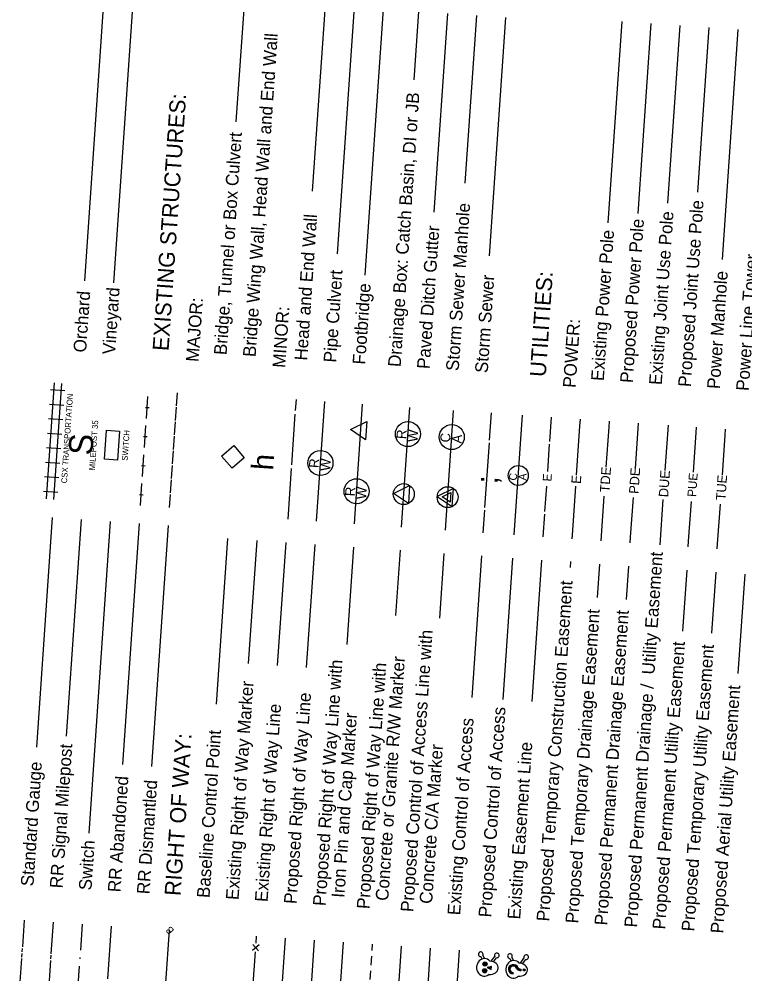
# Model space of a CAD drawing. Extents: x 2598107 to 2605763, y 726018 to 731166.
# Drawn here: x 2603520 to 2604643, y 728143 to 729620 of the extents above; entities that cross this region are included whole.
import ezdxf

# ---------------------------------------------------------------- set-up
doc = ezdxf.new("R2010")
doc.units = 0
for name, color, linetype in [('Prop Easement Permanent Drainage Utility', 7, 'Continuous'), ('Prop EOT', 7, 'Continuous'), ('Sheet Symbology CELL', 7, 'Continuous')]:
    doc.layers.add(name, color=color, linetype=linetype)

msp = doc.modelspace()

# ---------------------------------------------------------------- linework, layer by layer
at = {"layer": 'Prop Easement Permanent Drainage Utility'}
for p, q in [((2604519.7, 728921.8), (2604524.5, 728991.9)), ((2604511.7, 728806.7), (2604516.6, 728876.9))]:
    msp.add_line(p, q, dxfattribs=at)
at = {"layer": 'Prop EOT'}
msp.add_lwpolyline([(2603849.6, 728925.2), (2603833.3, 728943.9), (2603852, 728960.3), (2603868.4, 728941.5)], close=True, dxfattribs=at)
at = {"layer": 'Sheet Symbology CELL'}
for p, q in [((2603652.7, 729675.1), (2603621, 729215.1)), ((2603697.6, 729672), (2603665.9, 729212)), ((2603868.5, 729650.5), (2603855.5, 729461)), ((2603993.3, 729641.9), (2603973.4, 729353.9)), ((2604038.2, 729638.8), (2604011.9, 729256.8)), ((2604083.1, 729635.7), (2604054.7, 729223.9)), ((2604137.9, 729632), (2604130.6, 729526)), ((2604182.8, 729628.9), (2604161.6, 729321.5)), ((2604227.7, 729625.8), (2604209.8, 729366.1)), ((2604272.6, 729622.7), (2604247.2, 729254.1)), ((2604452.6, 729616.6), (2604431.1, 729305.2)), ((2604497.5, 729613.5), (2604477.2, 729319.6)), ((2604542.4, 729610.4), (2604523.4, 729335.4)), ((2604587.3, 729607.3), (2604569.7, 729352.5)), ((2604632.2, 729604.2), (2604607.7, 729248.4)), ((2603573.2, 729034.8), (2603574.7, 729057.3)), ((2603584.4, 729034), (2603585.9, 729056.5)), ((2603590.8, 729044.9), (2603568.3, 729046.4)), ((2603763.4, 729021.7), (2603764.8, 729041.9)), ((2603589.2, 729022.4), (2603566.8, 729024)), ((2603571.6, 729012.4), (2603573.2, 729034.8)), ((2603582.9, 729011.6), (2603584.4, 729034)), ((2603717, 729002.4), (2603719.3, 729036)), ((2603947.7, 729014.7), (2603948.9, 729031.5)), ((2603980, 728843.3), (2603992.8, 729028.5)), ((2604038.7, 728839.3), (2604051.4, 729024.4)), ((2603570.1, 728989.9), (2603571.6, 729012.4)), ((2603581.3, 728989.2), (2603582.9, 729011.6)), ((2603715.4, 729019.4), (2603721, 729019)), ((2603761.9, 728999.3), (2603763.3, 729019.5)), ((2603941.9, 728930.5), (2603947.3, 729009.1)), ((2604111.6, 728834.2), (2604124.4, 729019.4)), ((2604179.5, 728829.6), (2604192.3, 729014.7)), ((2604247.9, 728968.9), (2604250.8, 729010.7)), ((2604286, 728822.2), (2604298.7, 729007.4)), ((2603587.7, 729000), (2603565.2, 729001.5)), ((2603760.4, 728976.8), (2603761.7, 728997)), ((2604341, 728966.7), (2604343.6, 729004.3)), ((2604387.8, 728990.2), (2604388.5, 729001.2)), ((2604432.8, 728988.8), (2604433.4, 728998.1)), ((2604477.7, 728986.7), (2604478.3, 728995)), ((2603586.1, 728977.5), (2603563.7, 728979.1)), ((2603568.5, 728967.5), (2603570.1, 728989.9)), ((2603579.8, 728966.7), (2603581.3, 728989.2)), ((2603713.9, 728957.5), (2603716.2, 728991.1)), ((2604048.6, 728983.9), (2604048.6, 728983.9)), ((2604382.5, 728914.5), (2604387.8, 728990.2)), ((2604428.5, 728927.1), (2604432.8, 728988.8)), ((2604473.5, 728925), (2604477.7, 728986.7)), ((2604563.3, 728918.9), (2604567.5, 728980.6)), ((2604567.5, 728980.6), (2604568.1, 728988.9)), ((2604612.4, 728976.4), (2604613, 728985.8)), ((2603567, 728945), (2603568.5, 728967.5)), ((2603578.2, 728944.3), (2603579.8, 728966.7)), ((2603712.3, 728974.5), (2603717.9, 728974.1)), ((2603758.8, 728954.4), (2603760.2, 728974.6)), ((2604240.7, 728864.7), (2604247.6, 728964.4)), ((2604608.1, 728914.7), (2604612.4, 728976.4)), ((2603584.6, 728955.1), (2603562.2, 728956.6)), ((2603757.3, 728931.9), (2603758.7, 728952.1)), ((2604337.8, 728920.2), (2604340.7, 728962.3)), ((2603583.1, 728932.7), (2603560.6, 728934.2)), ((2603565.4, 728922.6), (2603567, 728945)), ((2603576.7, 728921.8), (2603578.2, 728944.3)), ((2603710.8, 728912.6), (2603713.1, 728946.2)), ((2603563.9, 728900.1), (2603565.4, 728922.6)), ((2603575.1, 728899.4), (2603576.7, 728921.8)), ((2603709.2, 728929.6), (2603714.8, 728929.2)), ((2603755.7, 728909.5), (2603757.1, 728929.7)), ((2603936.1, 728846.3), (2603941.5, 728924.9)), ((2603581.5, 728910.2), (2603559.1, 728911.8)), ((2603754.2, 728887), (2603755.6, 728907.2)), ((2603580, 728887.8), (2603557.5, 728889.3)), ((2603562.4, 728877.7), (2603563.9, 728900.1)), ((2603573.6, 728876.9), (2603575.1, 728899.4)), ((2603707.7, 728867.7), (2603710, 728901.4)), ((2604333.6, 728858.4), (2604336.3, 728897.7)), ((2604376.2, 728821.9), (2604381.4, 728897.7)), ((2603706.1, 728884.7), (2603711.7, 728884.3)), ((2603752.6, 728864.6), (2603754, 728884.8)), ((2604115.1, 728885.2), (2604115.1, 728885.2)), ((2604183, 728880.5), (2604183, 728880.5)), ((2604421.2, 728820.5), (2604425.4, 728882.2)), ((2604466.1, 728818.4), (2604470.4, 728880.1)), ((2604555.9, 728812.3), (2604560.2, 728874)), ((2604238, 728825.5), (2604240.4, 728860.2)), ((2604600.8, 728808.1), (2604605, 728869.8)), ((2603571.1, 728849.1), (2603546.6, 728493.6)), ((2603616, 728846), (2603592.9, 728510.4)), ((2604330.9, 728819.1), (2604333.3, 728853.9)), ((2603660.9, 728843), (2603627.7, 728360.5)), ((2603705.8, 728839.9), (2603680.1, 728466.9)), ((2603750.7, 728836.8), (2603725, 728463.8)), ((2603750.7, 728836.8), (2603725, 728463.8)), ((2603842.6, 728816.6), (2603824.9, 728560.2)), ((2604375.8, 728816), (2604376.2, 728821.9)), ((2604420.6, 728812.9), (2604421.2, 728820.5)), ((2604465.5, 728809.9), (2604466.1, 728818.4)), ((2603887.5, 728813.5), (2603874.3, 728622.9)), ((2603932.4, 728810.4), (2603919.2, 728619.8)), ((2603977.3, 728807.3), (2603964.1, 728616.7)), ((2604037.5, 728803.2), (2604027.1, 728652.5)), ((2604555.4, 728803.7), (2604555.9, 728812.3)), ((2604600.2, 728800.6), (2604600.8, 728808.1)), ((2604109.4, 728798.2), (2604102.5, 728697.2)), ((2604177.3, 728793.5), (2604170.4, 728693.4)), ((2604235.6, 728789.5), (2604220.5, 728570.6)), ((2604283.5, 728786.2), (2604268.4, 728567.3)), ((2604328.4, 728783.1), (2604313.3, 728564.2)), ((2604373.3, 728780.9), (2604372.7, 728771.5)), ((2604418.2, 728777), (2604414.6, 728725)), ((2604463.1, 728773.9), (2604459.5, 728721.9)), ((2604552.9, 728767.7), (2604546.4, 728673.1)), ((2604597.8, 728764.6), (2604591.3, 728670)), ((2604642.7, 728761.5), (2604632.1, 728607.8)), ((2603525.4, 728184.6), (2603528.2, 728226)), ((2603569.7, 728173.8), (2603573.1, 728222.9)), ((2603615.2, 728179.4), (2603618, 728219.8)), ((2603657.3, 728135.3), (2603662.9, 728216.7)), ((2603747.1, 728129.1), (2603752.7, 728210.5)), ((2603886.6, 728190.2), (2603887.4, 728201.2)), ((2603919.9, 728018.6), (2603932.3, 728198.1)), ((2603919.9, 728018.6), (2603932.3, 728198.1)), ((2603964.8, 728015.5), (2603977.1, 728195.1)), ((2603964.8, 728015.5), (2603977.1, 728195.1)), ((2603524.8, 728176.7), (2603525.2, 728182.3)), ((2603891.2, 728187.9), (2603881.1, 728179.1)), ((2603890.5, 728178.5), (2603881.8, 728188.5)), ((2604009.7, 728012.4), (2604022, 728192)), ((2604009.7, 728012.4), (2604022, 728192)), ((2604066.3, 728178.9), (2604066.9, 728188.9)), ((2604106.5, 728108.5), (2604111.8, 728185.8)), ((2604151.5, 728107.4), (2604156.7, 728182.7)), ((2604196.4, 728103.8), (2604201.6, 728179.6)), ((2603519.9, 728104.9), (2603524.1, 728166.6)), ((2603524.3, 728168.8), (2603524.7, 728174.5)), ((2603569.2, 728166), (2603569.6, 728171.6)), ((2603614.3, 728165.9), (2603614.4, 728168.2)), ((2603883.7, 728148.7), (2603885.7, 728176.8)), ((2604064.7, 728156.5), (2604065.6, 728170)), ((2604234.2, 728169.6), (2604236.3, 728165.8)), ((2604237.2, 728171.2), (2604239.8, 728166.5)), ((2604250.4, 728162.3), (2604255.9, 728169.9)), ((2604253.9, 728161.3), (2604258.7, 728167.9)), ((2604279.4, 728166.7), (2604281.5, 728162.8)), ((2604282.4, 728168.3), (2604285, 728163.5)), ((2604295.6, 728159.4), (2604301.1, 728167)), ((2604299, 728158.4), (2604303.9, 728165)), ((2603564.8, 728102), (2603569, 728163.7)), ((2603610.4, 728109.8), (2603613.5, 728154.7)), ((2604245.3, 728152.5), (2604245.3, 728152.5)), ((2604294.9, 728150), (2604296.8, 728149.9)), ((2604295, 728150.3), (2604296.9, 728150.2)), ((2604296.7, 728148.1), (2604296.9, 728150.2)), ((2603881.8, 728120.7), (2603883.7, 728148.7)), ((2604063.2, 728134), (2604064.1, 728147.5)), ((2604284.2, 728143), (2604284.3, 728145.1)), ((2604289.4, 728149.6), (2604289.4, 728149.6)), ((2604294.8, 728148.8), (2604296.7, 728148.7)), ((2604294.8, 728148.5), (2604296.7, 728148.4)), ((2604294.8, 728148.2), (2604296.7, 728148.1)), ((2604294.9, 728149.7), (2604296.8, 728149.6)), ((2604294.9, 728149.4), (2604296.8, 728149.3)), ((2604294.9, 728149.1), (2604296.8, 728149))]:
    msp.add_line(p, q, dxfattribs=at)
for points in [[(2604055.7, 728969.3), (2604032.5, 728985), (2604057.7, 728997.4)], [(2603651.8, 728939.2), (2603654.9, 728984.1), (2603675.4, 728982.7), (2603672.3, 728937.8)], [(2604122.2, 728870.6), (2604099, 728886.3), (2604124.2, 728898.7)], [(2604190.1, 728865.9), (2604192.1, 728894), (2604166.8, 728881.6)], [(2604186.7, 728872.9), (2604174.6, 728881.1), (2604187.7, 728887.5)], [(2604244.2, 728152.6), (2604250.6, 728149.7), (2604250.9, 728154.5)], [(2604245.3, 728152.5), (2604250.3, 728150.3), (2604250.5, 728154)], [(2604246.5, 728152.4), (2604249.9, 728150.9), (2604250.1, 728153.5)], [(2604247.6, 728152.4), (2604249.6, 728151.5), (2604249.7, 728153)], [(2604248.7, 728152.3), (2604249.2, 728152), (2604249.3, 728152.4)]]:
    msp.add_lwpolyline(points, close=True, dxfattribs=at)
for centre, radius in [((2604121.5, 728978.1), 19.4), ((2604189.4, 728973.4), 19.4), ((2603986.2, 728933.3), 19.4), ((2604292.3, 728914), 15.5), ((2604042.1, 728889.6), 19.4), ((2604115.1, 728885.2), 16.2), ((2604183, 728880.5), 16.2), ((2604240.2, 728147.6), 3.24), ((2604240.2, 728147.6), 2.86), ((2604240.9, 728158.1), 3.24), ((2604240.2, 728147.6), 2.48), ((2604240.9, 728158.1), 2.86), ((2604240.9, 728158.1), 2.48), ((2604240.9, 728158.1), 2.1), ((2604240.9, 728158.1), 1.71), ((2604240.9, 728158.1), 1.33), ((2604240.9, 728158.1), 0.948), ((2604240.9, 728158.1), 0.566), ((2604240.9, 728158.1), 0.183), ((2604301.5, 728148.9), 1.55), ((2604301.5, 728148.9), 1.2), ((2604240.2, 728147.6), 2.1), ((2604240.2, 728147.6), 1.71), ((2604240.2, 728147.6), 1.33), ((2604240.2, 728147.6), 0.948), ((2604240.2, 728147.6), 0.566), ((2604240.2, 728147.6), 0.183), ((2604301.5, 728148.9), 0.854), ((2604301.5, 728148.9), 0.509), ((2604301.5, 728148.9), 0.165)]:
    msp.add_circle(centre, radius, dxfattribs=at)
for centre, start, end in [((2604234.2, 728173.2), 326.2539, 270.1625), ((2604259.2, 728171.5), 261.9577, 205.8663), ((2604279.4, 728170.3), 326.2539, 270.1625), ((2604304.4, 728168.6), 261.9577, 205.8663)]:
    msp.add_arc(centre, 3.63, start, end, dxfattribs=at)
for centre, major_axis, ratio, start_param, end_param in [((2604239.9, 728152.9), (0.9, 13.6), 0.885014, 5.564242, 10.143721), ((2604285.1, 728149.9), (0.9, 13.6), 0.885014, 5.564242, 10.143721), ((2604247.7, 728152.3), (13.6, -0.9), 0.752542, 4.722735, 7.843636), ((2604284.7, 728150), (-7.78, 0.54), 0.9, 3.567618, 7.853982), ((2604284.7, 728150), (-7.44, 0.51), 0.9, 3.567618, 7.853982), ((2604284.7, 728150), (-7.1, 0.49), 0.9, 3.567618, 7.853982), ((2604284.7, 728150), (-6.75, 0.47), 0.9, 3.567618, 7.853982), ((2604284.7, 728150), (-6.41, 0.44), 0.9, 3.567618, 7.853982), ((2604284.7, 728150), (-6.07, 0.42), 0.9, 3.567618, 7.853982), ((2604284.7, 728150), (-5.72, 0.39), 0.9, 3.567618, 7.853982), ((2604284.7, 728150), (-5.38, 0.37), 0.9, 3.567618, 7.853982), ((2604295.2, 728153.4), (-5.84, 0.4), 0.9, 0.426026, 1.570796), ((2604295.2, 728153.4), (-5.49, 0.38), 0.9, 0.426026, 1.570796), ((2604295.2, 728153.4), (-5.15, 0.35), 0.9, 0.426026, 1.570796), ((2604295.2, 728153.4), (-4.81, 0.33), 0.9, 0.426026, 1.570796), ((2604295.2, 728153.4), (-4.46, 0.31), 0.9, 0.426026, 1.570796), ((2604295.2, 728153.4), (-4.12, 0.28), 0.9, 0.426026, 1.570796), ((2604295.2, 728153.4), (-3.78, 0.26), 0.9, 0.426026, 1.570796), ((2604295.2, 728153.4), (-3.43, 0.24), 0.9, 0.426026, 1.570796), ((2604292.9, 728149.4), (13.6, -0.9), 0.752542, 4.722735, 7.843636)]:
    msp.add_ellipse(centre, major_axis=major_axis, ratio=ratio, start_param=start_param, end_param=end_param, dxfattribs=at)

# ---------------------------------------------------------------- texts
at = {"layer": 'Prop Easement Permanent Drainage Utility'}
msp.add_text('DUE', height=14.74, rotation=86.0601, dxfattribs=at).set_placement((2604524.2, 728880))
at = {"layer": 'Sheet Symbology CELL'}
for s, height, rotation, p in [('Bridge Wing Wall, Head Wall and End Wall', 19.688, 86.0601, (2603885.8, 729096.9)), ('EXISTING STRUCTURES:', 24.75, 86.0601, (2603751.1, 729106.1)), ('Drainage Box: Catch Basin, DI or JB', 19.688, 86.0601, (2604110.2, 729081.4)), ('Bridge, Tunnel or Box Culvert', 19.688, 86.0601, (2603840.9, 729099.9)), ('Storm Sewer Manhole', 19.688, 86.0601, (2604200, 729075.2)), ('Proposed Joint Use Pole', 19.688, 86.0601, (2604559.2, 729050.5)), ('Head and End Wall', 19.688, 86.0601, (2603965.6, 729091.4)), ('Existing Joint Use Pole', 19.688, 86.0601, (2604514.2, 729053.6)), ('Proposed Power Pole', 19.688, 86.0601, (2604469.4, 729056.7)), ('Paved Ditch Gutter', 19.688, 86.0601, (2604155.1, 729078.3)), ('Existing Power Pole', 19.688, 86.0601, (2604424.5, 729059.8)), ('Power Line Tower', 19.688, 86.0601, (2604648.9, 729044.4)), ('Pipe Culvert', 19.688, 86.0601, (2604010.5, 729088.3)), ('Power Manhole', 19.688, 86.0601, (2604604, 729047.4)), ('Storm Sewer', 19.688, 86.0601, (2604244.9, 729072.1)), ('UTILITIES:', 24.75, 86.0601, (2604334.7, 729065.9)), ('Vineyard', 19.69, 86.0601, (2603668.4, 729100.8)), ('Footbridge', 19.69, 86.0601, (2604055.4, 729085.2)), ('Orchard', 19.69, 86.0601, (2603623.5, 729103.9)), ('MAJOR:', 19.69, 86.0601, (2603797.6, 729089.3)), ('MINOR:', 19.69, 86.0601, (2603931.6, 729080.1)), ('POWER:', 19.69, 86.0601, (2604380.9, 729049.2)), ('CSX TRANSPORTATION', 9, 86.0601, (2603593.9, 728901.6)), ('MILEPOST 35', 9, 86.0601, (2603637.1, 728921.6)), ('SWITCH', 9, 86.0601, (2603687.8, 728936.6)), ('R', 15.2, 86.0601, (2604118.7, 728969.9)), ('W', 15.2, 86.0601, (2604136.3, 728965.3)), ('C', 15.2, 86.0601, (2604186.5, 728964.7)), ('S', 37.1, 86.0601, (2603633.2, 728944.4)), ('A', 15.2, 86.0601, (2604204.4, 728963.3)), ('h', 33.7, 86.0601, (2603913.1, 728921.2)), ('R', 15.2, 86.0601, (2603983.4, 728925.2)), ('W', 15.2, 86.0601, (2604001, 728920.5)), ('TDE', 14.74, 86.0601, (2604433.2, 728887.5)), ('PDE', 14.74, 86.0601, (2604478.2, 728885.2)), (';', 33.7, 86.0601, (2604260.1, 728900.1)), ('C', 12.1, 86.0601, (2604289.9, 728905.9)), ('A', 12.1, 86.0601, (2604304.5, 728906.1)), ('E', 13.5, 86.0601, (2604343.5, 728904.4)), ('E', 14.7, 86.0601, (2604389, 728900.7)), ('PUE', 13.5, 86.0601, (2604567.4, 728880.5)), ('TUE', 14.74, 86.0601, (2604612.8, 728875.1)), ('R', 15.2, 86.0601, (2604039.3, 728881.4)), ('W', 15.2, 86.0601, (2604056.9, 728876.7)), ('Proposed Permanent Drainage /  Utility Easement', 19.688, 86.0601, (2604476, 728214.2)), ('Proposed Temporary Construction Easement', 19.688, 86.0601, (2604340.1, 728223.6)), ('Proposed Temporary Drainage Easement', 19.688, 86.0601, (2604384.9, 728220.5)), ('Proposed Permanent Drainage Easement', 19.688, 86.0601, (2604429.8, 728217.4)), ('Proposed Control of Access Line with', 19.688, 86.0601, (2604129.8, 728238.1)), ('Proposed Permanent Utility Easement', 19.688, 86.0601, (2604519.6, 728211.2)), ('Proposed Temporary Utility Easement', 19.688, 86.0601, (2604564.5, 728208.1)), ('Proposed Right of Way Line with', 19.688, 86.0601, (2603994.1, 728247.4)), ('Proposed Right of Way Line with', 19.688, 86.0601, (2604061.9, 728242.7)), ('  Concrete or Granite R/W Marker', 19.688, 86.0601, (2604090, 728240.8)), ('Existing Right of Way Marker', 19.688, 86.0601, (2603859.4, 728256.7)), ('Proposed Aerial Utility Easement', 19.688, 86.0601, (2604609.4, 728205)), ('Proposed Right of Way Line', 19.688, 86.0601, (2603949.2, 728250.5)), ('Existing Right of Way Line', 19.688, 86.0601, (2603904.3, 728253.6)), ('Proposed Control of Access', 19.688, 86.0601, (2604250.3, 728229.8)), ('  Iron Pin and Cap Marker', 19.688, 86.0601, (2604022.1, 728245.5)), ('Existing Control of Access', 19.688, 86.0601, (2604202.3, 728233.1)), ('Baseline Control Point', 19.688, 86.0601, (2603814.5, 728259.8)), ('RIGHT OF WAY:', 24.75, 86.0601, (2603769.6, 728262.9)), ('RR Signal Milepost', 19.688, 86.0601, (2603586.9, 728274.8)), ('  Concrete C/A Marker', 19.688, 86.0601, (2604157.9, 728236.1)), ('Existing Easement Line', 19.688, 86.0601, (2604295.2, 728226.7)), ('Standard Gauge', 19.688, 86.0601, (2603542, 728277.9)), ('RR Abandoned', 19.688, 86.0601, (2603676.7, 728268.7)), ('RR Dismantled', 19.688, 86.0601, (2603721.6, 728265.6)), ('Switch', 19.69, 86.0601, (2603631.8, 728271.7)), ('B', 11.3, 131.0602, (2603760.6, 728210))]:
    msp.add_text(s, height=height, rotation=rotation, dxfattribs=at).set_placement(p)

doc.saveas('drawing.dxf')
